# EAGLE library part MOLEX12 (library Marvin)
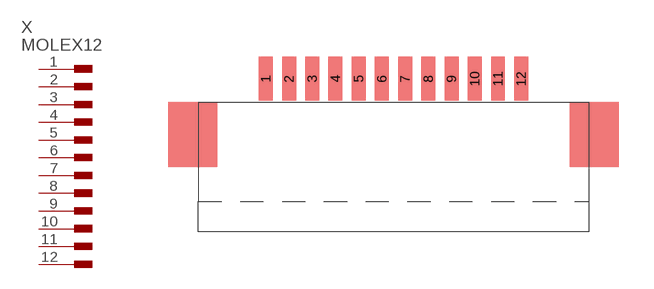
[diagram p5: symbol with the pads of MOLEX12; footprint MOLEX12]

Designator prefix X

## MOLEX12S  [MOLEX12]
1  -1
2  -2
3  -3
4  -4
5  -5
6  -6
7  -7
8  -8
9  -9
10  -10
11  -11
12  -12

## Footprint MOLEX12 (pad centres in mm)
smd 0.6 x 1.9: 1 -6,3; 2 -5,3; 3 -4,3; 4 -3,3; 5 -2,3; 6 -1,3; 7 0,3; 8 1,3; 9 2,3; 10 3,3; 11 4,3; 12 5,3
